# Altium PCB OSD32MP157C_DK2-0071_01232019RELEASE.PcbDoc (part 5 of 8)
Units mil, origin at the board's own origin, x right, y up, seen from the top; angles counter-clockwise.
Board outline 3976.38 x 2795.28 mil, 6 copper layers (Top Layer, Signal Layer 1, Signal Layer 2, Signal Layer 3, Signal Layer 4, Bottom Layer), stack 61.268 mil thick; 404 components, 418 nets, 1720 pads, 1233 vias.
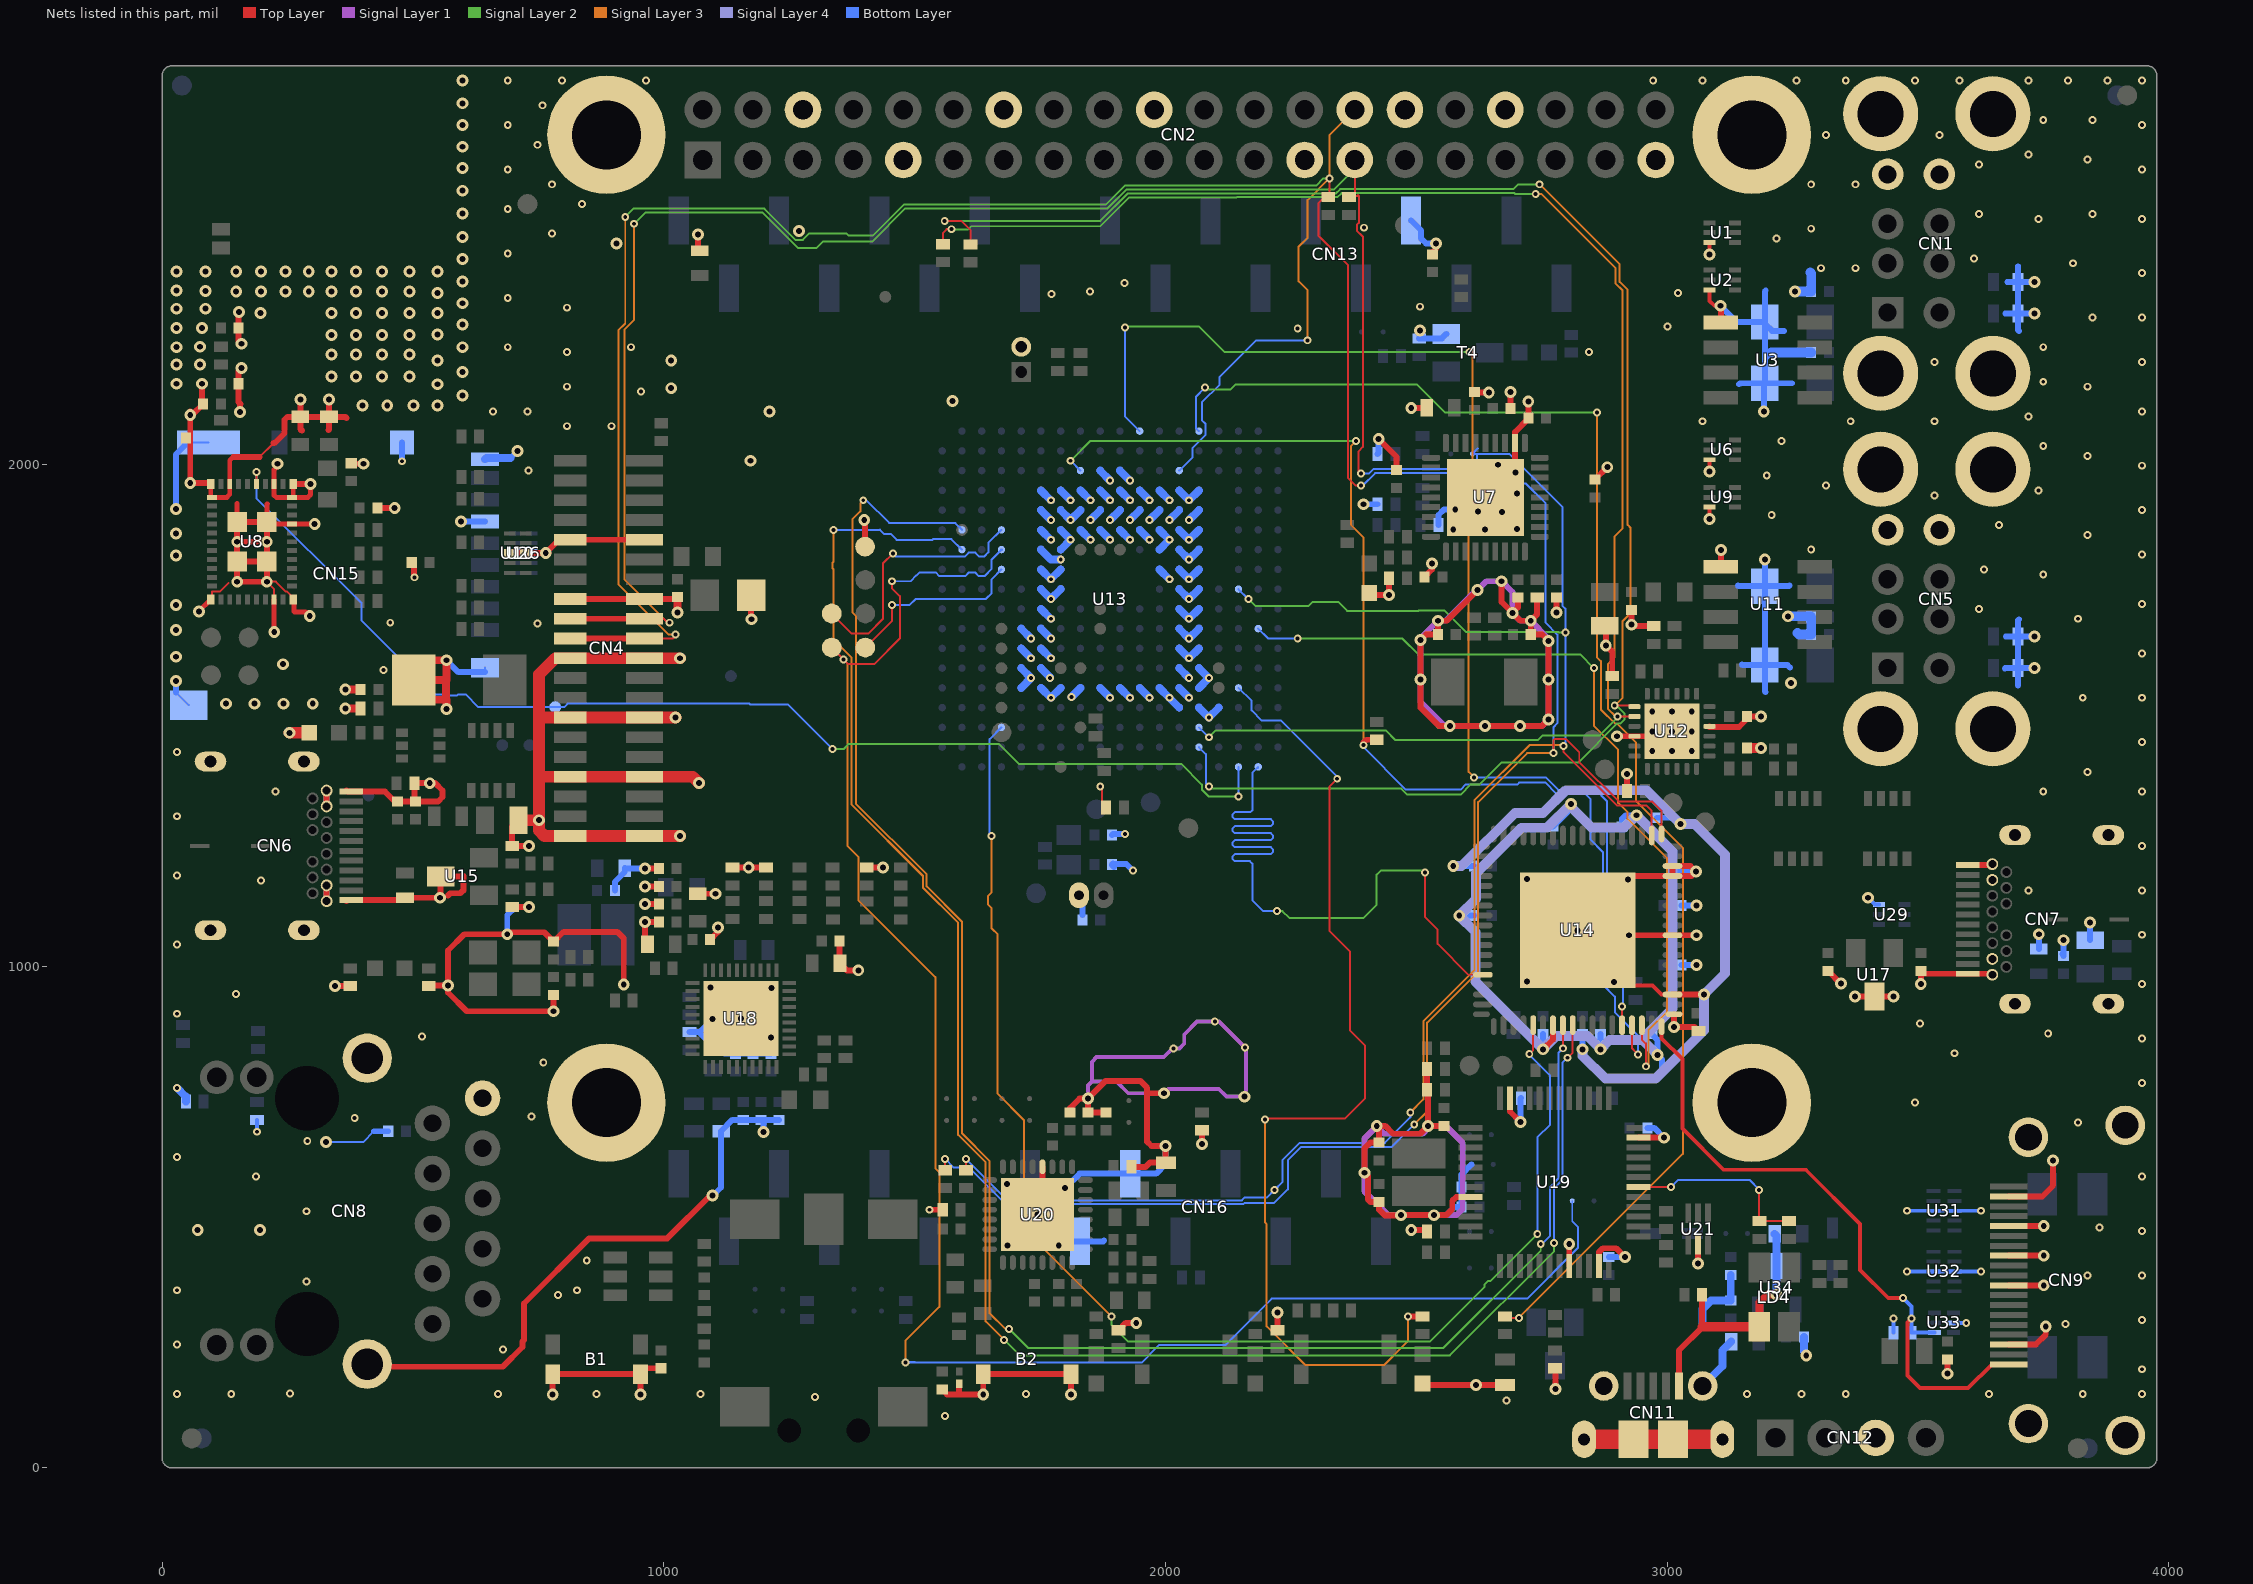
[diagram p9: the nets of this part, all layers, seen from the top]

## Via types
v1: diameter 15.75, hole 7.87, Top Layer to Bottom Layer, tented both sides, 803 vias
v2: diameter 23.62, hole 11.81, Top Layer to Bottom Layer, tented both sides, 417 vias
v3: diameter 15.75, hole 7.87, Top Layer to Bottom Layer, 13 vias

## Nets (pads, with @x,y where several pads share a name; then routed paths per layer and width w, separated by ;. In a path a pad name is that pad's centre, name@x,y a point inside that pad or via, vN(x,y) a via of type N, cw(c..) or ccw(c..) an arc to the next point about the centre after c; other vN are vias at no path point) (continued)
GND: B1.1 B1.2 B2.3 B2.4 C1.1 C7.1 C8.1 C19.1 C21.1 C23.1 C24.1 C25.1 C28.1 C29.1 C30.1 C34.1 C37.1 C38.1 C40.1 C45.1 C49.2 C50.1 C51.1 C52.2 C53.1 C54.1 C55.1 C56.1 C58.1 C59.1 C60.2 C61.2 C62.1 C65.1 C69.1 C70.2 C71.1 C74.1 C75.1 C76.2 C77.1 C78.1 C79.1 C80.1 C81.1 C82.1 C83.1 C84.1 C85.1 C86.1 C90.2 C91.2 C93.1 C94.1 C95.1 C96.2 C98.2 C99.2 C112.1 C114.1 C115.1 C117.1 C118.1 C123.1 C124.1 C133.1 C136.1 C137.1 C138.1 C140.1 C141.1 C142.1 C151.1 C154.1 C157.1 C160.1 C164.1 C166.1 C167.1 C168.1 C169.1 C170.1 C171.1 C172.1 C173.1 C174.1 C175.1 C176.1 C177.1 C178.1 C179.1 C180.1 C181.1 C182.1 C183.1 C184.1 C185.2 C186.1 C187.1 C188.1 C189.1 C190.1 CN1.B4 CN1.CH1 CN1.CH2 CN1.CH3 CN1.CH4 CN1.T4 CN2.6 CN2.9 CN2.14 CN2.20 CN2.25 CN2.30 CN2.34 CN2.39 CN3.2 CN4.1 CN4.2 CN4.7 CN4.8 CN4.13 CN4.14 CN4.19 CN4.20 CN4.25 CN4.26 CN4.31 CN4.32 CN5.B4 CN5.CH1 CN5.CH2 CN5.CH3 CN5.CH4 CN5.T4 CN6.A1 CN6.A12 CN6.B1 CN6.B12 CN6.SH1 CN6.SH2 CN6.SH3 CN6.SH4 CN7.A1 CN7.A12 CN7.B1 CN7.B12 CN7.SH1 CN7.SH2 CN7.SH3 CN7.SH4 CN8.1 CN8.15 CN8.16 CN9.2 CN9.5 CN9.8 CN9.11 CN9.17 CN9.20 CN9.21 CN9.22 CN9.23 CN11.5 CN11.6 CN11.7 CN11.8 CN11.9 CN11.10 CN11.11 CN12.3 CN13.7 CN15.6 CN15.9 CN15.10 CN15.12 CN15.13 CN15.14 CN16.6 CN16.7 CN95.2 H1.1 H2.1 H3.1 H4.1 LD1.2 LD2.2 LD4.1 LD7.2 LD8.2 R23.1 R24.1 R31.1 R36.1 R39.1 R45.1 R46.1 R48.1 R50.1 R51.1 R54.1 R57.1 R66.1 R67.1 R70.2 R80.1 R81.2 R82.1 R83.2 R84.1 R87.2 R91.1 R100.1 R110.2 R111.2 R112.1 R119.1 R129.1 R137.1 R139.1 R149.1 R155.2 R159.1 R162.1 R163.1 R164.1 R201.1 SB18.1 T4.2 TP2.1 U1.3 U2.3 U3.1 U6.3 U7.11 U7.37 U8.1 U8.12 U8.19 U8.21 U8.29 U8.32 U8.33 U8.35 U8.40 U8.42 U8.43 U8.44 U8.45 U8.46 U9.3 U10.3 U10.8 U11.1 U12.10 U12.22 U12.ep U13.D4 U13.E4 U13.E5 U13.E6 U13.E7 U13.E8 U13.E9 U13.E10 U13.E11 U13.E12 U13.E13 U13.E14 U13.E15 U13.F4 U13.F5 U13.F6 U13.F7 U13.F8 U13.F9 U13.F10 U13.F11 U13.F12 U13.F13 U13.F14 U13.F15 U13.G5 U13.G11 U13.G12 U13.G13 U13.G14 U13.G15 U13.H5 U13.H13 U13.H14 U13.H15 U13.J5 U13.J13 U13.J14 U13.J15 U13.J16 U13.K5 U13.K13 U13.K14 U13.K15 U13.K16 U13.L5 U13.L13 U13.L14 U13.L15 U13.M5 U13.M10 U13.M11 U13.M12 U13.M13 U13.M14 U13.M15 U13.N5 U13.N6 U13.N7 U13.N8 U13.N9 U13.N10 U13.N11 U13.N12 U13.N13 U13.N14 U13.N15 U13.P5 U13.P6 U13.P7 U13.P8 U14.43 U14.55 U14.57 U14.63 U14.69 U14.70 U14.e-Pad U15.3 U16.2 U17.3 U18.41 U19.8 U19.20 U19.23 U19.35 U19.47 U20.28 U20.33 U21.2 U23.2 U24.2 U25.2 U26.3 U26.8 U27.2 U28.2 U29.3 U30.2 U31.3 U31.8 U32.3 U32.8 U33.2 U34.2 U35.2 | length 28902
  Top Layer w3.54: v1@1873.16,1361.34 1872.41,1360.6 1872.41,1352.63 1873.62,1351.42 1873.62,1325.2 R201.1@1881.89,1316.93
  Top Layer w3.94: v2(56.1,2099.41) v2@56.1,2104.33 ; U8.12@96.97,1734.76 U8.12@96.97,1731.3 99.41,1731.3 99.41,1747.05 115.16,1747.05 131.89,1763.78 ; 194.54,2015.75 222.1,2043.31 ; v2(195.87,2302.17) v2@199.8,2298.23 ; U8.19@223.43,1731.3 223.43,1751.97 v2(208.66,1766.73) 226.88,1766.73 246.57,1747.05 249.02,1747.05 261.32,1734.74 U8.21@261.32,1731.3 ; v2@273.62,2131.89 v2(275.59,2129.92) ; v2@333.66,2298.23 v2(337.6,2302.17) ; CN8.16@408.97,207.09 CN8.16@408.86,207.09 CN8.16@414.17,201.77
  Top Layer w7.87: U14.e-Pad@2736.22,986.22 v2(2821.85,1071.85) ; U14.e-Pad@2891.73,1141.73 v2(2821.85,1071.85) ; U14.57@3010.83,943.9 2989.17,943.9 2971.46,961.61 2932.09,961.61 v2(2821.85,1071.85) ; v2(3084.65,1891.73) U9.3@3084.65,1915.35 ; v2(3084.65,1986.22) U6.3@3084.65,2009.84 ; U2.3@3084.65,2348.43 3084.65,2326.77 3094.49,2316.93 v2(3106.3,2316.93) ; v2(3084.65,2419.29) U1.3@3084.65,2442.91
  Top Layer w9.84: v2(73.35,1707.68) U8.12@96.97,1731.3 ; U8.42@96.97,1961.61 96.97,1937.48 U8.1@99.41,1935.04 128.95,1935.04 134.84,1940.94 U8.40@134.84,1961.61 134.84,2008.86 141.73,2015.75 ; U8.44@148.62,1807.09 U8.44@149.62,1807.09 ; U8.43@149.62,1885.83 149.62,1923.22 ; 209.65,1922.24 208.67,1921.27 U8.45@208.67,1885.83 212.61,1881.89 U8.29@258.86,1881.89 v2(304.13,1881.89) ; v2(223.43,1666.34) U8.19@223.43,1731.3 ; 223.43,1938.98 U8.35@223.43,1961.61 223.43,1990.16 230.31,1997.05 v2(230.31,2001.97) ; 227.36,1936.02 228.35,1935.04 U8.32@258.86,1935.04 ; U8.21@261.32,1731.3 262.81,1729.81 262.81,1707.67 263.91,1706.56 286.06,1706.56 v2(294.3,1698.32) ; U8.33@261.32,1961.61 261.32,1937.5 U8.32@258.86,1935.04 ; v2(295.77,1961.61) 295.77,1940.45 290.35,1935.04 U8.32@258.86,1935.04
  Top Layer w11.81: v2@56.1,2104.33 v2@56.1,2106.3 ; v2(79.72,2161.42) 79.72,2123.03 C24.1@81.69,2121.06 60.04,2099.41 v2(56.1,2099.41) v2(56.1,1963.58) 95,1963.58 U8.42@96.97,1961.61 ; 141.73,2015.75 194.54,2015.75 ; v2@152.56,2187.01 C19.1@152.56,2161.42 152.56,2125 155.51,2122.05 ; v2@152.56,2247.05 C8.1@152.56,2272.64 v2@152.56,2298.23 ; v2(155.51,2105.31) 155.51,2122.05 ; 156.5,2121.06 155.51,2122.05 ; v2(208.66,1846.46) U8.45@208.67,1885.83 U8.43@149.62,1885.83 v2(149.61,1846.46) ; 222.1,2043.31 224.41,2043.31 244.09,2062.99 244.09,2089.57 250,2095.47 C28.1@275.59,2095.47 ; U8.33@261.32,1961.61 v2(295.77,1961.61) ; v2(275.59,2129.92) C28.1@275.59,2095.47 ; 278.54,2067.91 275.59,2070.87 C28.1@275.59,2095.47 ; CN6.B1@327.95,1129.92 CN6.B1@327.95,1161.42 ; CN6.B12@327.95,1318.9 CN6.B12@327.95,1350.39 ; 331.69,2068.9 332.68,2069.88 C29.1@332.68,2095.47 ; v2(332.68,2129.92) C29.1@332.68,2095.47 ; v2(344.49,960.63) R66.1@375,960.63 ; 367.13,2093.5 365.16,2095.47 C29.1@332.68,2095.47 ; CN6.A12@367.32,1129.92 369.29,1131.89 CN6.A12@377.17,1131.89 479.33,1131.89 U16.2@484.25,1136.81 v2(554.13,1136.81) 555.12,1137.8 U15.3@555.12,1179.13 599.41,1179.13 600.39,1180.12 600.39,1151.57 594.49,1145.67 574.19,1145.67 569.57,1141.06 ; CN6.A1@367.32,1350.39 369.29,1348.43 CN6.A1@377.17,1348.43 443.9,1348.43 463.58,1328.74 C69.1@469.49,1328.74 C70.2@504.92,1328.74 ; C37.1@376.97,2002.95 377.95,2001.97 v2(401.57,2001.97) ; CN8.16@414.17,201.77 679.13,201.77 718.5,241.14 718.5,251.8 721.46,254.75 721.46,327.76 851.38,457.68 1006.92,457.68 1092.55,543.31 v2(1097.44,543.31) ; C45.1@429.13,1913.39 v2(463.58,1913.39) ; C49.2@497.64,1804.77 501.77,1800.64 501.77,1777.84 502.95,1776.66 v1(502.95,1775.59) ; R67.1@531.5,960.63 532.48,961.61 v2(569.88,961.61) ; U10.8@692.52,1823.82 U10.3@724.8,1823.82 764.72,1823.82 v2(764.8,1823.9) ; R57.1@697.83,1118.11 v2(731.3,1118.11) ; C71.1@710.63,1291.34 697.83,1278.54 R48.1@697.83,1240.16 v2(731.3,1240.16) ; v2@770.75,1823.9 v2(764.8,1823.9) ; v2(778.54,146.65) B1.2@778.54,187.01 B1.1@953.74,187.01 ; C86.1@780.51,942.91 v2(780.51,910.43) 607.28,910.43 569.88,947.83 v2(569.88,961.61) ; CN4.26@813.98,1732.28 1023.62,1732.28 C51.1@1027.56,1736.22 ; H3.1@885.83,728.35 H3.1@885.83,762.8 ; v2(920.28,963.58) 920.28,1056.1 907.48,1068.9 800.2,1068.9 C82.1@780.51,1049.21 761.81,1067.91 691.93,1067.91 v2(687.99,1063.98) 602.36,1063.98 569.88,1031.5 v2(569.88,961.61) ; v2(953.74,146.65) B1.1@953.74,187.01 ; CN4.31@961.61,1850.39 791.29,1850.39 v2(764.8,1823.9) ; v2(962.6,1124.02) C77.1@990.16,1124.02 ; v2(962.6,1159.45) C75.1@990.16,1159.45 ; v2(962.6,1194.88) C74.1@990.16,1194.88 ; C80.1@967.52,1044.29 962.6,1049.21 v2(962.6,1088.58) C78.1@990.16,1088.58 ; C114.1@994.09,198.82 965.55,198.82 B1.1@953.74,187.01 ; C76.2@1067.91,1144.69 v2(1103.35,1144.69) ; v2(1067.91,2458.66) 1067.91,2430.51 U23.2@1071.85,2426.57 ; C79.1@1092.52,1053.15 1108.27,1068.9 v2(1108.27,1077.76) ; R50.1@1136.81,1196.85 v2(1169.29,1196.85) R51.1@1203.74,1196.85 ; C52.2@1174.21,1740.16 1174.21,1690.94 v2(1175.2,1691.93) ; C81.1@1350.39,1050.2 1350.39,1006.89 C85.1@1351.38,1005.91 1365.16,992.13 v2(1387.8,992.13) ; v2(1399.61,1889.76) 1401.28,1888.09 TP2.1@1401.28,1836.68 ; R54.1@1404.53,1196.85 v2(1437.01,1196.85) ; v1(1529.53,514.76) R87.2@1556.1,514.76 ; C115.1@1555.12,156.5 1564.96,146.65 1588.58,146.65 ; U35.2@1588.58,167.81 1588.58,146.65 ; U20.28@1754.92,600.39 1754.92,514.76 v2(1745.08,504.92) 1749.02,504.92 1801.18,557.09 v2(1800.2,558.07) ; C94.1@1810.04,708.66 1810.04,717.52 1828.74,736.22 v2(1845.47,736.22) ; v2(1812.01,146.65) B2.4@1812.01,187.01 B2.3@1636.81,187.01 v2(1636.81,146.65) 1588.58,146.65 ; C96.2@1881.89,708.66 C95.1@1845.47,708.66 v2(1845.47,736.22) ; R110.2@1906.5,274.61 1921.26,289.37 v2(1941.93,289.37) ; R84.1@1932.09,600.39 1960.63,600.39 1969.49,609.25 R83.2@2000,609.25 ; v2(1997.05,747.05) 1964.57,747.05 1963.58,748.03 ; R83.2@2000.98,608.27 R83.2@2000,609.25 ; v2(2072.83,645.67) R82.1@2072.83,673.23 ; R111.2@2223.43,274.61 v2(2223.43,310.04) ; LD1.2@2406.5,1744.09 2410.43,1740.16 v2(2445.87,1740.16) R23.1@2445.87,1773.62 ; v2(2425.2,2051.18) 2460.63,2015.75 C38.1@2460.63,1989.17 ; v2(2490.15,474.41) 2518.7,474.41 R91.1@2521.65,471.46 ; v2(2490.16,2113.19) C23.1@2520.67,2113.19 ; LD7.2@2512.8,168.31 2515.75,165.35 v2(2619.09,165.35) LD8.2@2677.17,165.35 ; C50.1@2516.73,1776.57 2531.5,1791.34 v2(2531.5,1803.15) ; R80.1@2521.65,795.28 R81.2@2521.65,753.94 2523.62,751.97 v2(2523.62,682.09) ; C1.1@2534.45,2421.26 C1.1@2532.48,2419.29 2527.56,2419.29 2539.37,2431.1 v2(2539.36,2440.94) ; C93.1@2555.12,682.09 v2(2523.62,682.09) ; U19.8@2608.27,540.35 2579.72,540.35 2571.85,532.48 2571.85,515.75 2560.04,503.94 v2(2535.43,503.94) v2(2469.49,503.94) 2470.47,502.95 2437.99,502.95 2426.18,514.76 C99.2@2426.18,530.51 2408.46,530.51 2403.54,535.43 2403.54,581.69 v2(2396.65,588.58) 2396.65,636.81 2408.46,648.62 C98.2@2426.18,648.62 2426.18,682.09 2437.99,682.09 2453.74,666.34 2507.87,666.34 v2(2523.62,682.09) ; C21.1@2616.14,2144.69 2617.13,2143.7 v2(2644.68,2143.7) ; v2(2622.05,1750) 2561.02,1688.98 v2(2543.31,1688.98) C58.1@2543.31,1661.42 2519.68,1661.42 v2(2508.86,1650.59) 2508.86,1515.55 2545.08,1479.33 2750.98,1479.33 v2(2763.78,1492.13) v2(2763.78,1648.62) 2750.98,1661.42 C59.1@2728.35,1661.42 v2(2728.35,1688.98) ; U7.37@2637.8,1935.04 2696.85,1994.09 U7.11@2696.85,2043.31 2696.85,2064.96 2723.43,2091.54 C30.1@2723.43,2093.5 v2(2723.43,2125.98) ; v2(2670.28,1767.72) 2670.28,1726.38 v2(2691.93,1704.72) ; U19.47@2687.01,737.2 2687.01,710.63 v2(2707.68,689.96) ; C25.1@2687.99,2112.2 v2(2687.99,2144.69) ; C53.1@2702.76,1735.24 2702.76,1715.55 v2(2691.93,1704.72) ; R24.1@2741.14,1735.24 2741.14,1701.77 v2(2728.35,1688.98) ; v2(2752.95,834.65) 2772.64,854.33 U14.43@2772.64,882.87 ; R112.1@2776.57,198.82 2777.56,197.83 v2(2777.56,157.48) ; v2(2779.53,1705.71) C54.1@2779.53,1735.24 ; U19.20@2805.12,402.56 v2(2805.12,446.85) ; C40.1@2856.3,1970.47 v2(2880.91,1995.08) ; U19.23@2864.17,402.56 2864.17,430.12 2872.05,437.99 2898.62,437.99 v2(2916.34,420.28) ; C55.1@2875.98,1679.13 2877.95,1677.17 v2(2877.95,1639.76) 2890.75,1626.97 R36.1@2890.75,1578.74 ; U14.e-Pad@2891.73,1141.73 2930.12,1180.12 U14.69@3010.83,1180.12 ; v2(2900.59,1458.66) U12.10@2935.04,1458.66 2960.63,1458.66 v2(2970.47,1468.5) ; R46.1@2920.28,1349.41 v2(2920.28,1383.86) ; v2(2924.21,1062.01) U14.63@3010.83,1062.01 v2(3059.06,1062.01) ; C56.1@2929.13,1710.63 v2(2929.13,1681.1) 2932.09,1678.15 R31.1@2973.43,1678.15 ; U19.35@2942.91,658.46 v2(2994.09,658.46) ; U14.57@3010.83,943.9 v2(3073.82,943.9) v2@3072.83,944.88 ; U14.55@3013.78,904.53 v2(3013.78,878.94) 3055.12,878.94 R70.2@3062.99,871.06 ; CN11.5@3023.62,163.39 3023.62,234.25 3070.87,281.5 3069.88,282.48 R100.1@3069.88,345.47 ; v2(3062.01,407.48) U21.2@3062.01,444.69 ; U12.22@3084.65,1478.35 3084.65,1477.17 3143.5,1477.17 3159.45,1493.11 C62.1@3159.45,1498.03 v2(3187.01,1498.03) ; v2(3106.3,2316.93) 3107.28,2315.94 U3.1@3107.28,2283.66 ; U11.1@3107.28,1796.46 v2(3107.28,1829.72) ; C83.1@3320.87,991.14 v2(3346.46,965.55) ; v2(3375,939.96) U17.3@3413.39,939.96 v2(3451.77,939.96) ; v2(3505.91,964.57) C84.1@3505.91,991.14 3511.81,985.24 CN7.A1@3599.21,985.24 3646.46,985.24 CN7.B12@3648.43,983.27 ; v2(3559.06,187.99) C112.1@3559.06,216.54 ; CN7.A12@3599.21,1201.77 3646.46,1201.77 CN7.B1@3648.43,1203.74 ; CN9.17@3681.1,246.06 3735.24,246.06 3754.92,265.75 v2(3754.92,282.34) ; CN9.11@3681.1,364.17 v2(3750.98,364.17) ; CN9.8@3681.1,423.23 v2(3750.98,423.23) ; CN9.5@3681.1,482.28 v2(3750.98,482.28) ; CN9.2@3681.1,541.34 3748.03,541.34 3769.68,562.99 v2(3769.68,613.19) ; U8.44@149.62,1807.09 U8.46@208.67,1807.09 ; U8.44@149.62,1807.09 148.62,1807.09 149.61,1806.1 v2(149.61,1766.73) v2(208.66,1766.73) U8.46@208.67,1807.09 ; U8.44@149.62,1807.09 v2(149.61,1846.46) ; v2(149.61,1846.46) v2(208.66,1846.46) U8.46@208.67,1807.09 ; C28.1@275.59,2095.47 C29.1@332.68,2095.47 ; C70.2@504.92,1328.74 550.2,1328.74 559.06,1337.6 559.06,1350.39 544.29,1365.16 v2(533.46,1365.16) R45.1@502.95,1365.16 502.95,1330.71 C70.2@504.92,1328.74 ; v2(1845.47,736.22) 1880.91,771.65 1949.8,771.65 1963.58,757.87 1963.58,748.03 ; 1963.58,748.03 1963.58,650.39 1972.24,641.73 v2(2000,641.73) R83.2@2000,609.25 ; v2(2691.93,1704.72) 2707.68,1688.98 v2(2728.35,1688.98) ; U14.69@3010.83,1180.12 U14.70@3010.83,1199.8 3046.75,1199.8 v2(3057.58,1188.98) 3048.72,1180.12 U14.69@3010.83,1180.12
  Top Layer w15.75: v2(365.16,1513.78) R39.1@395.67,1513.78 ; v2(365.16,1552.17) C61.2@395.67,1552.17 ; C60.2@481.3,1591.54 C60.2@501.97,1570.87 ; C60.2@500.98,1531.5 565.94,1531.5 ; v2(566.93,1512.8) 566.93,1526.57 563.98,1529.53 565.94,1531.5 ; 566.93,1531.5 565.94,1531.5 ; v2(566.93,1610.24) 566.93,1570.87 ; v2@567.91,1610.24 501.97,1610.24 C60.2@501.97,1570.87 ; v2(1027.56,1705.71) C51.1@1027.56,1736.22 ; LD4.1@3184.06,281.5 3184.06,329.72 3199.8,345.47 v2(3218.5,345.47) ; C60.2@501.97,1570.87 566.93,1570.87 ; 565.94,1531.5 565.94,1569.88 566.93,1570.87
  Top Layer w19.68: 3070.87,281.5 LD4.1@3184.06,281.5 ; C65.1@3159.45,1435.04 v2(3187.01,1435.04)
  Top Layer w23.62: v2(253.94,1465.55) LD2.2@293.31,1465.55 ; C71.1@710.63,1291.34 v2(751.6,1291.34) ; v2(1023.62,1496.06) 753.47,1496.06 751.6,1494.19 ; v2(1032.48,1259.84) 762.24,1259.84 751.6,1270.48 v2(751.6,1291.34) ; v2(1032.48,1614.17) 809.33,1614.17 809.22,1614.29 783.58,1614.29 751.6,1582.31 751.6,1494.19 ; v2(1070.08,1365.75) 1057.87,1377.95 752.46,1377.95 751.6,1378.81 ; v2(751.6,1291.34) 751.6,1378.81 ; 751.6,1378.81 751.6,1494.19
  Top Layer w39.37: CN11.9@2834.65,57.09 CN11.10@2933.07,57.09 CN11.11@3011.81,57.09 CN11.8@3110.24,57.09
  Signal Layer 1 w7.87: v2(1845.47,736.22) 1845.47,762.2 1853.54,770.28 ; 1853.54,770.28 1853.54,809.58 1862.86,818.9 1996.65,818.9 2013.98,836.22 v1(2015.94,836.22) 2027.76,836.22 2037.6,846.06 2037.6,864.37 2062.99,889.76 v1(2098.43,889.76) 2107.09,889.76 v1(2158.66,838.19) 2160.63,836.22 2160.63,743.31 v2(2157.48,740.16) 2122.05,740.16 2106.3,755.91 2005.91,755.91 v2(1997.05,747.05) 1925.98,747.05 1902.76,770.28 1853.54,770.28
  Signal Layer 1 w11.81: v2(2421.26,682.09) v2@2421.26,681.1 ; v2@2421.75,681.59 v2@2421.26,681.1 ; v2@2522.83,681.3 v2@2523.62,681.3 ; v2(2523.62,682.09) v2@2523.62,681.3 ; v2@2620.28,1748.23 2617.91,1748.23 2558.66,1688.98 v2(2543.31,1688.98) 2508.86,1654.53 v2(2508.86,1650.59) v2(2508.86,1571.85) 2508.86,1526.57 2556.1,1479.33 v2(2566.93,1479.33) v2(2636.81,1479.33) v2(2706.69,1479.33) 2750.98,1479.33 v2(2763.78,1492.13) v2(2763.78,1571.85) v2(2763.78,1648.62) 2763.78,1653.54 v2(2728.35,1688.98) 2707.68,1688.98 v2(2691.93,1704.72) 2691.93,1746.06 v2(2670.28,1767.72) 2639.76,1767.72 v2(2622.05,1750) ; v2@2421.26,681.1 2421.26,680.12 2435.04,666.34 2512.8,666.34 2523.62,677.17 v2@2523.62,681.3 ; v2@2421.26,681.1 2396.65,656.5 v2(2396.65,588.58) 2396.65,551.97 2444.69,503.94 v2(2469.49,503.94) v2(2535.43,503.94) 2580.31,503.94 2592.72,516.34 2592.72,648.23 2559.65,681.3 v2@2523.62,681.3
  Signal Layer 2 w7.87: 2543.06,1478.49 v2@2556,1478.49
  Signal Layer 2 w11.81: CN6.B1@327.95,1129.92 CN6.B1@327.95,1161.42 ; CN6.B12@327.95,1318.9 CN6.B12@327.95,1350.39
  Signal Layer 3 w11.81: CN6.B1@327.95,1129.92 CN6.B1@327.95,1161.42 ; CN6.B12@327.95,1318.9 CN6.B12@327.95,1350.39
  Signal Layer 4 w11.81: CN6.B1@327.95,1129.92 CN6.B1@327.95,1161.42 ; CN6.B12@327.95,1318.9 CN6.B12@327.95,1350.39
  Signal Layer 4 w19.68: v2(2573.82,1199.8) 2590.55,1199.8 2696.75,1306 2753.06,1306 2798.04,1350.98 2959.06,1350.98 v2(3026.57,1283.46) 3054.92,1283.46 3115.35,1223.03 3115.35,985.43 v2(3073.82,943.9) 3073.82,872.44 2977.56,776.18 2877.17,776.18 2831.69,821.65 v2(2831.69,834.65) ; 2950.98,855.91 3011.02,915.94 3011.02,1229.13 v2(2938.98,1301.18) 2914.37,1276.57 2849.1,1276.57 2808.27,1317.41 v2(2808.27,1323.43) 2761.02,1276.18 2709.84,1276.18 2619.29,1185.63 2619.29,1134.45 v2(2585.83,1100.98) 2618.31,1068.5 2618.31,969.29 v2(2752.95,834.65) 2779.13,860.83 2841.7,860.83 2867.13,835.4 v2(2867.13,834.65) 2885.43,852.95 2951.18,852.95 v2(2980.65,823.49)
  Bottom Layer w3.94: CN15.13@27.56,1546.26 CN15.13@53.15,1520.67 ; CN15.12@51.18,2044.29 CN15.12@92.52,2044.29 ; v2(326.77,649.61) 400.59,649.61 422.24,671.26 ; CN15.14@643.7,1586.61 CN15.14@643.7,1595.47
  Bottom Layer w7.87: v1(188.98,670.28) R163.1@188.98,693.9 ; v2(3400.59,1136.81) 3414.37,1123.03 U29.3@3422.24,1123.03 ; R164.1@3451.77,269.69 v1(3451.77,298.23) ; v1(3478.35,391.73) U32.8@3531.5,391.73 U32.3@3572.83,391.73 v1(3625.98,391.73) ; v1(3478.35,512.8) U31.8@3531.5,512.8 U31.3@3572.83,512.8 v1(3625.98,512.8) ; U33.2@3570.87,289.37 v1(3596.46,289.37)
  Bottom Layer w11.81: CN15.13@27.56,1546.26 v2(27.56,1568.9) ; v2(27.56,1911.42) 27.56,2020.67 CN15.12@51.18,2044.29 ; CN6.B1@327.95,1129.92 CN6.B1@327.95,1161.42 ; CN6.B12@327.95,1318.9 CN6.B12@327.95,1350.39 ; 422.24,671.26 C183.1@450.79,671.26 ; v1(478.35,2006.89) CN15.10@478.35,2044.29 ; v2(566.93,1610.24) 590.55,1586.61 CN15.14@643.7,1586.61 ; v2(595.47,1886.81) 589.57,1886.81 CN15.6@643.7,1886.81 ; v2(687.99,1063.98) 687.99,1102.36 703.74,1118.11 v2(731.3,1118.11) ; 694.49,2013.39 v2(708.66,2027.56) ; U26.3@704.33,1823.82 U26.8@736.61,1823.82 764.72,1823.82 v2(764.8,1823.9) ; C157.1@902.56,1151.57 902.56,1168.31 922.24,1187.99 C151.1@922.24,1195.87 923.23,1194.88 v2(962.6,1194.88) ; R155.2@1051.18,869.09 1071.85,869.09 ; v2(1097.44,543.31) 1098.43,543.31 1114.17,559.06 C180.1@1114.17,671.26 1136.81,693.9 C179.1@1158.46,693.9 C178.1@1193.9,693.9 C178.1@1196.06,693.9 ; v2(1199.02,669.88) 1199.02,690.94 C178.1@1196.06,693.9 ; v2(1213.58,858.27) C174.1@1213.58,825.79 C175.1@1178.15,825.79 C176.1@1142.72,825.79 1121.06,825.79 C173.1@1098.43,848.43 1090.55,848.43 1070.87,868.11 1071.85,869.09 ; C177.1@1229.33,693.9 C178.1@1196.06,693.9 ; 1776.57,449.8 1778.58,451.81 CN16.7@1829.92,451.81 1876.02,451.81 1877.95,453.74 ; v2(1800.2,558.07) 1828.92,586.79 CN16.6@1929.92,586.79 1981.48,586.79 2000,605.31 v2(2000,641.73) ; CN3.2@1827.76,1141.73 1834.65,1134.84 C7.1@1834.65,1102.36 ; C90.2@1893.7,1261.81 1895.67,1263.78 v3(1919.29,1263.78) ; C91.2@1895.67,1204.72 C91.2@1894.92,1203.97 ; C91.2@1897.83,1197.64 1893.7,1201.77 C91.2@1893.7,1202.76 C91.2@1894.92,1203.97 ; v3(1935.04,1190.94) 1922.01,1203.97 C91.2@1894.92,1203.97 ; v2(2394.68,1921.26) R137.1@2423.23,1921.26 ; R129.1@2423.23,2021.65 2425.2,2023.62 v2(2425.2,2051.18) ; CN13.7@2489.92,2486.77 2509.84,2466.85 2509.84,2450.79 2519.68,2440.94 v2(2539.36,2440.94) ; v2(2507.87,2267.71) 2507.87,2253.93 R119.1@2505.91,2251.97 2551.18,2251.97 T4.2@2560.04,2260.83 ; v2(2535.43,503.94) 2560.04,503.94 2576.77,520.67 C184.1@2590.55,520.67 C182.1@2590.55,560.04 2590.55,585.63 SB18.1@2610.24,605.31 ; R139.1@2544.29,1879.92 2544.29,1899.61 2555.12,1910.43 v2(2577.76,1910.43) ; v2(2573.82,1199.8) C154.1@2615.16,1199.8 ; v2(2585.83,1100.98) 2614.76,1100.98 C164.1@2615.16,1101.38 ; v2(2707.68,689.96) 2707.68,736.22 R159.1@2708.66,737.2 ; v2(2752.95,834.65) C172.1@2752.95,865.16 ; C142.1@2772.64,1278.54 2808.27,1314.17 v2(2808.27,1323.43) ; v2(2831.69,834.65) C171.1@2831.69,865.16 ; v2(2867.13,834.65) C170.1@2867.13,865.16 ; C186.1@2883.86,420.28 v2(2916.34,420.28) ; C141.1@2910.43,1278.54 2910.43,1294.29 2917.32,1301.18 v2(2938.98,1301.18) ; C181.1@2960.63,678.15 2974.41,678.15 v2(2994.09,658.46) ; C169.1@2969.49,865.16 2980.65,854 v2(2980.65,823.49) 2990.16,813.98 2990.16,794.29 ; C140.1@2980.31,1296.26 3013.78,1296.26 v2(3026.57,1283.46) ; v2(3013.78,878.94) v2@3014.76,879.92 ; R149.1@3017.72,1191.93 3054.63,1191.93 v2(3057.58,1188.98) ; C168.1@3028.54,1002.95 v2(3059.06,1002.95) ; C160.1@3028.54,1121.06 v2(3059.06,1121.06) ; v2(3106.3,2316.93) 3138.78,2284.45 C118.1@3194.88,2284.45 ; 3141.73,1758.86 3142.72,1757.87 C133.1@3194.88,1757.87 ; 3143.7,2160.43 3145.67,2162.4 C124.1@3194.88,2162.4 ; 3149.61,1601.38 3150.59,1600.39 C138.1@3194.88,1600.39 ; v2(3192.91,2106.3) 3192.91,2160.43 C124.1@3194.88,2162.4 ; v2(3194.88,1811.02) C133.1@3194.88,1757.87 ; 3195.87,1547.24 3194.88,1548.23 C138.1@3194.88,1600.39 ; 3196.85,2347.44 3194.88,2345.47 C118.1@3194.88,2284.45 ; 3207.68,2223.43 3194.88,2210.63 ; 3233.27,2266.73 3209.65,2266.73 C118.1@3194.88,2281.5 ; 3244.09,1758.86 3243.11,1757.87 C133.1@3194.88,1757.87 ; 3245.08,1595.47 3240.16,1600.39 C138.1@3194.88,1600.39 ; 3249.02,2162.4 C124.1@3194.88,2162.4 ; C136.1@3286.42,1697.83 C136.1@3287.4,1696.85 ; 3673.23,1593.5 3674.21,1594.49 U28.2@3699.8,1594.49 ; 3674.21,2301.18 U25.2@3699.8,2301.18 ; 3675.2,1657.48 U27.2@3699.8,1657.48 ; 3678.15,2364.17 U24.2@3699.8,2364.17 ; 3699.8,1560.04 U28.2@3699.8,1594.49 ; 3699.8,2395.67 U24.2@3699.8,2364.17 ; 3701.77,1691.93 3699.8,1689.96 U27.2@3699.8,1657.48 ; 3701.77,2266.73 3699.8,2268.7 U25.2@3699.8,2301.18 ; v2(3732.28,1594.49) U28.2@3699.8,1594.49 ; v2(3732.28,1657.48) U27.2@3699.8,1657.48 ; v2(3732.28,2301.18) U25.2@3699.8,2301.18 ; v2(3732.28,2364.17) U24.2@3699.8,2364.17 ; U30.2@3741.14,1034.45 v2(3741.14,1063.98) ; C167.1@3788.39,1024.61 C167.1@3790.35,1022.64 ; C167.1@3790.35,1020.67 C167.1@3790.35,1022.64 ; v2(3790.35,1052.17) C167.1@3790.35,1022.64 ; C166.1@3843.5,1052.17 v2(3843.5,1087.6) ; 1071.85,869.09 v2(1097.44,894.69) 1071.85,869.09 ; C138.1@3194.88,1600.39 C133.1@3194.88,1757.87 ; C124.1@3194.88,2162.4 3194.88,2210.63 ; 3194.88,2210.63 C118.1@3194.88,2281.5 ; C118.1@3194.88,2281.5 C118.1@3194.88,2284.45 ; U28.2@3699.8,1594.49 U27.2@3699.8,1657.48 ; U25.2@3699.8,2301.18 U24.2@3699.8,2364.17
  Bottom Layer w15.75: v1(29.53,757.87) 47.24,740.16 R162.1@47.24,730.31 ; CN15.9@643.7,2010.83 646.26,2013.39 694.49,2013.39 ; U13.P5@1712.6,1555.12 v1(1732.28,1574.8) U13.P6@1712.6,1594.49 ; U13.P7@1712.6,1633.86 v1(1732.28,1614.17) ; U13.P8@1712.6,1673.23 v1(1732.28,1653.54) ; U13.N5@1751.97,1555.12 v1(1771.65,1535.43) U13.M5@1791.34,1555.12 ; U13.N6@1751.97,1594.49 1769.68,1576.78 v1(1769.68,1574.8) ; U13.N7@1751.97,1633.86 v1(1771.65,1614.17) ; U13.N8@1751.97,1673.23 v1(1771.65,1653.54) ; U13.N9@1751.97,1712.6 v1(1771.65,1692.91) ; U13.N10@1751.97,1751.97 v1(1771.65,1732.28) U13.M10@1791.34,1751.97 ; U13.N11@1751.97,1791.34 v1(1771.65,1771.65) U13.M11@1791.34,1791.34 ; U13.N12@1751.97,1830.71 1771.66,1811.02 v1(1791.33,1811.02) ; U13.N13@1751.97,1870.08 v1(1771.65,1850.39) ; U13.N14@1751.97,1909.45 v1(1771.65,1889.76) ; U13.N15@1751.97,1948.82 v1(1771.65,1929.13) ; U13.M12@1791.34,1830.71 v1(1811.02,1850.39) U13.M13@1791.34,1870.08 ; U13.M14@1791.34,1909.45 v1(1811.02,1889.76) U13.L14@1830.71,1909.45 ; U13.M15@1791.34,1948.82 v1(1811.02,1929.13) ; v1(1812.58,1536.99) U13.L5@1830.71,1555.12 ; U13.L13@1830.71,1870.08 v1(1850.39,1850.39) ; U13.L15@1830.71,1948.82 v1(1850.39,1929.13) ; v1(1850.39,1889.76) U13.K14@1870.08,1909.45 ; U13.K5@1870.08,1555.12 v1(1889.76,1535.43) ; U13.K13@1870.08,1870.08 v1(1889.76,1850.39) ; U13.K15@1870.08,1948.82 v1(1889.76,1929.13) ; U13.K16@1870.08,1988.19 v1(1889.76,1968.5) ; v1(1889.76,1889.76) U13.J14@1909.45,1909.45 ; U13.J5@1909.45,1555.12 v1(1929.13,1535.43) ; U13.J13@1909.45,1870.08 v1(1929.13,1850.39) ; U13.J15@1909.45,1948.82 v1(1929.13,1929.13) ; U13.J16@1909.45,1988.19 v1(1929.13,1968.5) ; v1(1929.13,1889.76) U13.H14@1948.82,1909.45 ; U13.H5@1948.82,1555.12 v1(1968.5,1535.43) ; U13.H13@1948.82,1870.08 v1(1968.5,1850.39) ; U13.H15@1948.82,1948.82 v1(1968.5,1929.13) ; v1(1968.5,1889.76) U13.G14@1988.19,1909.45 ; U13.G5@1988.19,1555.12 v1(2007.87,1535.43) U13.F4@2027.56,1515.75 ; U13.G11@1988.19,1791.34 v1(2007.87,1771.65) ; U13.G12@1988.19,1830.71 v1(2007.87,1850.39) U13.G13@1988.19,1870.08 ; U13.G15@1988.19,1948.82 v1(2007.87,1929.13) ; v1(2007.87,1889.76) U13.F14@2027.56,1909.45 ; U13.F5@2027.56,1555.12 v1(2047.24,1535.43) ; U13.F6@2027.56,1594.49 v1(2047.24,1574.8) ; U13.F7@2027.56,1633.86 v1(2047.24,1614.17) U13.E7@2066.93,1633.86 ; U13.F8@2027.56,1673.23 v1(2047.24,1653.54) U13.E8@2066.93,1673.23 ; U13.F9@2027.56,1712.6 v1(2047.24,1692.91) U13.E9@2066.93,1712.6 ; U13.F10@2027.56,1751.97 v1(2047.24,1732.28) U13.E10@2066.93,1751.97 ; U13.F11@2027.56,1791.34 v1(2047.24,1771.65) U13.E11@2066.93,1791.34 ; U13.F12@2027.56,1830.71 v1(2047.24,1811.02) U13.E12@2066.93,1830.71 ; U13.F13@2027.56,1870.08 v1(2047.24,1850.39) U13.E13@2066.93,1870.08 ; U13.F15@2027.56,1948.82 v1(2047.24,1929.13) U13.E15@2066.93,1948.82 ; v1(2047.24,1889.76) U13.E14@2066.93,1909.45 ; U13.E4@2066.93,1515.75 v1(2086.61,1496.06) U13.D4@2106.3,1515.75 ; U13.E5@2066.93,1555.12 v1(2086.61,1574.8) U13.E6@2066.93,1594.49 ; CN11.7@3070.87,163.39 3110.24,202.76 3110.24,234.25 C190.1@3127.95,251.97 ; 3070.87,281.5 3070.87,316.93 3087.6,333.66 C188.1@3126.97,333.66 ; C188.1@3126.97,333.66 C187.1@3126.97,384.84 ; C185.2@3214.57,466.54 3218.5,462.6 U34.2@3218.5,402.56 v2(3218.5,345.47) ; C189.1@3272.64,260.83 3272.64,232.28 3277.56,227.36 v2(3277.56,224.41)
  Bottom Layer w19.68: 3207.68,2223.43 C123.1@3287.4,2223.43 ; v2(3241.14,1697.83) C136.1@3286.42,1697.83 ; v2(3254.92,2345.47) C117.1@3287.4,2345.47 3287.4,2380.91 3285.43,2382.87 ; 3259.84,1664.37 3262.8,1661.42 C137.1@3287.4,1661.42 C136.1@3287.4,1696.85
  other v1: 1561.02,103.35 2680.12,134.84 1301.18,141.73 29.53,147.64 137.8,147.64 669.29,147.64 866.14,147.64 1072.83,147.64 1722.44,147.64 3159.45,147.64 3267.72,147.64 3356.3,147.64 3641.73,147.64 3828.74,147.64 3946.85,147.64 254.92,148.62 3946.85,196.85 679.13,236.22 29.53,246.06 3794.29,287.4 3946.85,295.28 789.37,344.49 29.53,354.33 826.77,354.33 287.4,372.05 3838.58,383.86 3946.85,383.86 846.46,413.39 3946.85,472.44 3862.2,479.33 287.4,511.81 187.01,580.71 3946.85,580.71 29.53,620.08 289.37,651.57 3818.9,688.98 383.88,697.87 736.22,700.79 3494.09,728.35 3946.85,767.72 759.84,808.07 3572.83,826.77 3946.85,856.3 517.72,860.24 3759.84,866.14 3503.94,885.83 29.53,905.51 147.64,944.88 3946.85,964.57 29.53,1043.31 3946.85,1062.99 3720.47,1151.57 3946.85,1151.57 196.85,1171.26 29.53,1181.1 3946.85,1240.16 29.53,1299.21 226.38,1348.43 3750,1348.43 3946.85,1348.43 1870.08,1358.27 3838.58,1387.8 29.53,1427.17 3946.85,1446.85 3828.74,1535.43 3946.85,1535.43 440.94,1590.55 3946.85,1624.02 748.03,1683.07 454.72,1685.04 3818.9,1692.91 3622.05,1712.6 3946.85,1722.44 3750,1781.5 3631.89,1791.34 3946.85,1820.87 3287.4,1830.71 3838.58,1860.24 3661.42,1879.92 3208.66,1899.61 3946.85,1909.45 3533.46,1938.98 3740.16,1948.82 3316.93,1958.66 3198.82,1978.35 730.31,1988.19 3946.85,1998.03 3838.58,2017.72 3750,2037.4 3228.35,2047.24 807.09,2076.77 895.67,2076.77 3070.87,2086.61 3366.14,2086.61 3533.46,2086.61 3720.47,2096.46 659.45,2106.3 728.35,2106.3 3946.85,2106.3 954.72,2145.67 807.09,2155.51 3838.58,2155.51 3750,2165.35 3533.46,2204.72 3946.85,2204.72 807.09,2224.41 2844.49,2224.41 688.98,2234.25 935.04,2234.25 3750,2234.25 2263.78,2271.65 3000.98,2275.59 3848.43,2293.31 3946.85,2293.31 807.09,2312.99 2507.87,2314.96 688.98,2332.68 1772.64,2340.55 3021.65,2342.52 1849.41,2345.47 1918.31,2362.2 3946.85,2381.89 3307.09,2391.73 3375.98,2391.73 3809.06,2401.57 3612.2,2411.42 688.98,2421.26 3218.5,2450.79 777.56,2460.63 3287.4,2470.47 2395.67,2472.44 3740.16,2490.16 3946.85,2490.16 3622.05,2500 3848.43,2500 688.98,2509.84 836.61,2519.69 777.56,2559.06 3287.4,2559.06 3375.98,2559.06 688.98,2588.58 3946.85,2588.58 3622.05,2598.43 3838.58,2608.27 3720.47,2618.11 748.03,2637.8 3316.93,2657.48 3543.31,2657.48 688.98,2677.17 3946.85,2677.17 3750,2687.01 3848.43,2687.01 757.87,2716.54 688.98,2765.75 797.24,2765.75 964.57,2765.75 2972.44,2765.75 3070.87,2765.75 3257.87,2765.75 3356.3,2765.75 3494.09,2765.75 3582.68,2765.75 3720.47,2765.75 3799.21,2765.75 3877.95,2765.75 3946.85,2765.75
  other v2: 1685.04,443.9 1787.4,443.9 70.87,474.41 194.88,474.41 1684.06,565.94 1153.54,895.67 1214.57,956.69 1093.5,957.68 2894.68,968.5 2720.47,969.49 2922.24,1173.23 2720.47,1174.21 2970.47,1429.13 3009.84,1429.13 3049.21,1429.13 3009.84,1468.5 3049.21,1468.5 2970.47,1507.87 3009.84,1507.87 3049.21,1507.87 126.97,1523.62 184.06,1523.62 242.13,1523.62 300.2,1523.62 3247.05,1564.96 241.14,1602.36 27.56,1617.13 27.56,1670.28 27.56,1720.47 27.56,1818.9 27.56,1863.19 2573.82,1871.06 2636.81,1871.06 2700.79,1872.05 2671.26,1905.51 2623.03,1906.5 2700.79,1942.91 2697.83,1984.25 2663.39,2000 1173.23,2007.87 1210.63,2106.3 399.61,2118.11 448.82,2118.11 500.98,2118.11 549.21,2118.11 1575.79,2126.97 598.43,2137.8 1014.76,2152.56 549.21,2160.43 28.54,2161.42 337.6,2176.18 386.81,2176.18 437.99,2176.18 493.11,2176.18 598.43,2185.04 158.46,2192.91 28.54,2199.8 75.79,2199.8 549.21,2207.68 1014.76,2207.68 337.6,2219.49 386.81,2219.49 437.99,2219.49 493.11,2219.49 28.54,2234.25 598.43,2234.25 75.79,2235.24 158.46,2241.14 337.6,2258.86 386.81,2258.86 437.99,2258.86 493.11,2258.86 549.21,2259.84 28.54,2272.64 79.72,2272.64 598.43,2279.53 386.81,2302.17 437.99,2302.17 493.11,2302.17 549.21,2302.17 153.54,2304.13 28.54,2311.02 86.61,2311.02 598.43,2321.85 549.21,2342.52 147.64,2345.47 196.85,2345.47 246.06,2345.47 292.32,2345.47 337.6,2345.47 386.81,2345.47 437.99,2345.47 493.11,2345.47 86.61,2346.46 28.54,2347.44 598.43,2365.16 28.54,2384.84 86.61,2384.84 147.64,2384.84 196.85,2384.84 246.06,2384.84 292.32,2384.84 337.6,2384.84 386.81,2384.84 437.99,2384.84 493.11,2384.84 549.21,2384.84 598.43,2410.43 905.51,2440.94 598.43,2453.74 1269.88,2466.14 598.43,2500.98 598.43,2546.26 598.43,2591.54 598.43,2633.86 598.43,2677.17 598.43,2720.47 598.43,2765.75
HDMI_CEC: U13.H18 U14.50 | length 2531.2
  Top Layer w3.94: U14.50@2910.43,882.87 v1(2910.43,920.28)
  Signal Layer 2 w3.94: v1(1919.29,2273.62) 1921.26,2275.59 2066.93,2275.59 2118.11,2224.41 v1(2606.29,2224.41)
  Signal Layer 3 w3.94: v1(2606.29,2224.41) 2612.2,2218.49 2612.2,1986.22 2604.33,1978.35 2604.33,1387.6 v1(2615.35,1376.57)
  Bottom Layer w3.94: v1(1919.29,2273.62) 1919.29,2096.46 U13.H18@1948.82,2066.93 ; v1(2615.35,1376.57) 2758.09,1376.57 2782.7,1351.97 2857.85,1351.97 2880.17,1329.64 2880.17,1008.07 2912.4,975.84 2912.4,922.24 v1(2910.43,920.28)
HDMI_INT: U13.B8 U14.52 | length 1658.7
  Top Layer w3.94: 2949.8,853.94 U14.52@2949.8,882.87 ; 2950,853.94 2957.87,846.06 v1(2957.87,800.79)
  Signal Layer 2 w3.94: v1(2263.78,1653.54) 2472.44,1653.54 2503.94,1622.05 2826.77,1622.05 v1(2854.33,1594.49)
  Signal Layer 3 w3.94: v1(2854.33,1594.49) 2854.33,1479.87 2902.56,1431.64 2902.56,1325.79 2921.26,1307.09 2921.26,1293.84 3000,1215.1 3000,909.45 2962.93,872.38 2962.93,805.84 v1(2957.87,800.79)
  Bottom Layer w3.94: U13.B8@2185.04,1673.23 2204.72,1653.54 v1(2263.78,1653.54)
HDMI_NRST: R40.2 U13.L16 U14.51 | length 2390.7
  Top Layer w3.94: U14.51@2930.12,882.87 2930.12,836.42 2937.99,828.54 v1(2942.13,824.41)
  Top Layer w11.81: v1(2395.1,1440.84) 2395.1,1446.29 2400.59,1451.77 R40.2@2421.26,1451.77
  Signal Layer 2 w3.94: v1(1811.02,2007.87) 1850.39,2047.24 v1(2379.92,2047.24)
  Signal Layer 3 w3.94: v1(2379.92,2047.24) 2370.08,2037.4 2370.08,1879.47 2395.1,1854.45 v1(2395.1,1440.84)
  Bottom Layer w3.94: v1(1811.02,2007.87) U13.L16@1830.71,1988.19 ; v1(2395.1,1440.84) 2395.1,1436.59 2479.53,1352.17 2588.39,1352.17 2599.02,1362.8 2701.97,1362.8 2705.92,1366.75 2756.78,1366.75 2779.44,1344.09 2836.61,1344.09 2847.64,1333.07 2847.64,1252.56 2872.3,1227.9 2872.3,963.13 2895.87,939.57 2895.87,908.07 2942.13,861.81 v1(2942.13,824.41)
HPD: CN9.19 R164.2 U14.54 U33.4 | length 1325.1
  Top Layer w7.87: U14.54@2989.17,879.92 2989.17,856.3 3030.51,814.96 3030.51,676.63 3112.65,594.49 3276.57,594.49 3384.84,486.22 3384.84,394.69 3440.94,338.58 v1(3470.47,338.58) ; v1(3487.2,298.23) 3479.33,290.35 3479.33,184.06 3503.94,159.45 3600.39,159.45 3647.64,206.69 CN9.19@3681.1,206.69
  Bottom Layer w7.87: v1(3470.47,338.58) 3487.2,321.85 v1(3487.2,298.23) R164.2@3487.2,269.69 U33.4@3533.46,269.69
I2C1_SCL: CN2.28 CN4.21 CN4.22 R1.2 R85.2 SB8.1 U13.F16 U14.1 | length 7494.1
  Top Layer w3.94: CN4.21@961.61,1653.54 1017.72,1653.54 1023.62,1659.45 v1(1023.62,1661.42) ; R85.2@1561.02,593.5 v1(1561.02,616.14) ; v1(2326.77,2570.87) 2326.77,2535.43 R1.2@2324.8,2533.46 2316.93,2533.46 2305.12,2521.65 2305.12,2456.97 2364.17,2397.92 2364.17,1973.43 2379.33,1958.27 v1(2389.76,1958.27) ; v1(2773.62,1425.2) 2773.62,1451.06 2775.32,1452.76 2799.01,1452.76 2825,1426.77 2825,1407.09 2903.35,1328.74 2969.49,1328.74 2989.17,1309.06 U14.1@2989.17,1263.78
  Top Layer w11.81: CN4.22@813.98,1653.54 CN4.21@961.61,1653.54
  Signal Layer 2 w3.94: v1(923.23,2494.09) 939.57,2510.43 1200.54,2510.43 1262.54,2448.43 1277.22,2448.43 1289.82,2461.02 1363.98,2461.02 1368.31,2456.69 1416.76,2456.69 1478.57,2518.5 1881.44,2518.5 1919.39,2556.45 2300.54,2556.45 2314.96,2570.87 v1(2326.77,2570.87)
  Signal Layer 3 w3.94: v1(923.23,2494.09) 923.23,2281.5 909.45,2267.72 909.45,1761.81 1009.84,1661.42 v1(1023.62,1661.42) ; v1(1561.02,616.14) 1560.43,616.73 v1@1561.22,616.73 ; v1(2283.46,2248.03) 2283.46,2347.69 2265.75,2365.41 2265.75,2435.04 2283.46,2452.76 2283.46,2527.56 v1(2326.77,2570.87) 2326.77,2656.69 CN2.28@2377.56,2707.48 ; v1(2496.06,685.04) 2521.65,710.63 2521.65,887.8 2623.23,989.37 2623.23,1327.25 2721.17,1425.2 v1(2773.62,1425.2)
  Bottom Layer w3.94: v1(1561.02,616.14) 1578.42,598.74 1608.63,598.74 1678.94,528.43 1679.5,528.43 1682.04,525.89 2155.45,525.89 2157.99,528.43 2216.9,528.43 2244.09,555.62 2244.09,613.34 2270.95,640.2 2451.22,640.2 v1(2496.06,685.04) ; U13.F16@2027.56,1988.19 2053.64,2014.27 2053.64,2033.06 2080.22,2059.64 2080.22,2081.2 2072.83,2088.58 2072.83,2124.21 2108.27,2159.65 2108.27,2175 2181.3,2248.03 v1(2283.46,2248.03) ; v1(2389.76,1958.27) 2392.91,1958.27 2417.91,1983.27 2625,1983.27 2629.92,1978.35 2629.92,1966.54 2625.98,1962.6 ; 2612.2,1962.6 2625.98,1962.6 ; v1(2773.62,1425.2) 2773.62,1476.91 2781.5,1484.79 2781.5,1661.42 2757.87,1685.04 2757.87,1923.23 2718.5,1962.6 2625.98,1962.6
I2C1_SDA: CN2.27 CN4.23 CN4.24 R2.2 R86.2 SB7.1 U13.C10 U14.2 | length 7162.7
  Top Layer w3.94: CN4.23@961.61,1692.91 1000.13,1692.91 1008,1685.04 v1(1011.81,1685.04) ; R86.2@1602.36,593.5 v1(1602.36,616.14) ; CN2.27@2377.56,2607.48 2377.56,2534.06 2378.94,2535.43 2385.83,2535.43 ; 2384.11,2537.6 2385.83,2535.88 2385.83,2535.43 ; v1(2389.76,1982.87) 2385.04,1982.87 2385.04,2026.77 2393.7,2035.43 2393.7,2454.92 2381.89,2466.73 2381.89,2478.15 2385.83,2482.09 2385.83,2535.43 ; v1(2793.31,1438.98) 2793.31,1427.64 2900.08,1320.87 2958.66,1320.87 2969.49,1310.04 U14.2@2969.49,1260.83
  Top Layer w11.81: CN4.24@813.98,1692.91 CN4.23@961.61,1692.91
  Signal Layer 2 w3.94: v1(940.94,2480.31) 963.19,2502.56 1197.27,2502.56 1268.17,2431.66 1303.94,2431.66 1317.15,2444.88 1415.53,2444.88 1481.67,2511.02 1884.54,2511.02 1922.09,2548.58 2335.98,2548.58 2377.56,2590.16 CN2.27@2377.56,2607.48 ; v1(2165.35,1732.28) 2179.13,1718.5 2285.43,1718.5 2293.31,1726.38 2344.49,1726.38 2362.2,1708.66 2504.13,1708.66 2504.58,1709.11 2556.64,1709.11 2599.41,1666.34 2783.46,1666.34 2784.45,1665.35 v1(2797.24,1665.35)
  Signal Layer 3 w3.94: v1(940.94,2480.31) 940.94,2288.63 921.26,2268.95 921.26,1852.64 921.26,1771.78 1008,1685.04 v1(1011.81,1685.04) ; v1(2488.19,708.66) 2514.17,734.65 2514.17,890.89 2615.75,992.47 2615.75,1330.91 2725.79,1440.94 2791.34,1440.94 v1(2793.31,1438.98)
  Bottom Layer w3.94: v1(1602.36,616.14) 1685.14,533.37 2152.35,533.37 2158.35,539.37 2202.76,539.37 v1(2217.52,554.13) 2233.24,569.85 2233.24,613.62 2267.69,648.07 2437.44,648.07 2488.19,698.82 v1(2488.19,708.66) ; U13.C10@2145.67,1751.97 v1(2165.35,1732.28) ; v1(2389.76,1982.87) 2406.38,1982.87 2414.65,1991.14 2617.13,1991.14 2621.06,1995.08 2621.06,2021.65 ; 2623.03,2032.48 SB7.1@2612.2,2021.65 2621.06,2021.65 ; v1(2793.31,1438.98) 2797.24,1442.91 v1(2797.24,1665.35) 2797.24,1713.05 2791.34,1718.95 2791.34,1915.8 2685.49,2021.65 2621.06,2021.65
I2C4_SCL: R5.2 U12.7 U13.E2 | length 3497.1
  Top Layer w3.94: v1(1560.04,2486.22) 1592.72,2486.22 1611.61,2467.32 R5.2@1611.61,2438.98 ; v1(2895.67,1519.69) 2933.07,1519.69 U12.7@2935.04,1517.72
  Signal Layer 2 w3.94: v1(1560.04,2486.22) 1870.32,2486.22 1924.8,2540.7 2339.91,2540.7 2348.43,2549.21 2693.7,2549.21 2703.54,2559.05 2743.89,2559.05 2745.26,2557.68 2747.24,2557.68 2746.06,2558.86 v1(2746.06,2559.05) ; v1(2086.61,1358.27) 2090.55,1354.33 2470.47,1354.33 2482.28,1342.52 2588.39,1342.52 2608.66,1362.8 2626.57,1362.8 2669.9,1406.12 2822.57,1406.12 2900.7,1484.25 2907.28,1484.25 2915.35,1492.32 2915.35,1503.74 2899.41,1519.69 v1(2895.67,1519.69)
  Signal Layer 3 w3.94: v1(2746.06,2559.05) 2746.06,2558.86 2905.51,2399.41 2905.51,2364.37 2921.26,2348.62 2921.26,1879.92 2927.17,1874.02 2927.17,1704.19 2911.42,1688.44 2911.42,1535.43 v1(2895.67,1519.69)
  Bottom Layer w3.94: U13.E2@2066.93,1437.01 2080.71,1423.23 2080.71,1364.17 v1(2086.61,1358.27)
I2C4_SDA: R7.2 U12.8 U13.E3 | length 3298.6
  Top Layer w3.94: R7.2@1556.89,2439.57 1556.89,2462.4 1563.98,2469.49 v1(1573.82,2469.49) ; v1(2901.57,1498.03) U12.8@2935.04,1498.03
  Signal Layer 2 w3.94: v1(1573.82,2469.49) 1574.21,2469.09 1606.48,2469.09 1612.77,2475.39 1870.07,2475.39 1927.5,2532.83 2142.17,2532.83 2142.57,2533.22 2343.01,2533.22 2351.13,2541.34 2695.56,2541.34 2697.33,2539.57 2733.07,2539.57 2738.18,2544.68 v1(2738.18,2539.37) ; v1(2086.61,1456.69) 2100.39,1470.47 2438.98,1470.47 2458.66,1450.79 2742.13,1450.79 2751.97,1460.63 2865.94,1460.63 2901.57,1496.26 v1(2901.57,1498.03)
  Signal Layer 3 w3.94: v1(2738.18,2539.37) 2750.01,2539.37 2897.64,2391.73 2897.64,2361.11 2911.42,2347.33 2911.42,1873.03 2895.67,1857.28 2895.67,1616.14 2881.89,1602.36 2881.89,1513.98 2897.84,1498.03 v1(2901.57,1498.03)
  Bottom Layer w3.94: U13.E3@2066.93,1476.38 v1(2086.61,1456.69)
I2S2_CK: U13.U12 U14.45 | length 3692.1
  Top Layer w3.94: v1(2801.91,817.84) 2812.01,827.94 U14.45@2812.01,882.87
  Signal Layer 2 w3.94: v1(1678.35,255.51) 1709.45,224.41 2566.93,224.41 2774.8,432.28 v1(2774.8,448.43)
  Signal Layer 3 w3.94: v1(1338.58,1870.08) 1338.58,1806.89 1336.61,1804.92 1336.61,1793.51 1338.58,1791.54 1338.58,1651.18 1374.02,1615.75 1374.02,1322.83 1516.73,1180.12 1516.73,1156.5 1586.61,1086.61 1586.61,664.27 1641.73,609.15 1641.73,292.13 v1(1678.35,255.51)
  Bottom Layer w3.94: v1(1338.58,1870.08) 1430.4,1870.08 1430.75,1870.43 1438.98,1862.2 1452.22,1862.2 1464.03,1850.39 1535.43,1850.39 1536.91,1851.87 1573.33,1851.87 U13.U12@1594.49,1830.71 ; v1(2774.8,448.43) 2774.8,557.37 2791.54,574.1 2791.54,807.47 v1(2801.91,817.84)
I2S2_SDO: U13.R3 U14.41 | length 2708.7
  Top Layer w3.94: v1(2725.39,825.2) 2733.27,833.07 U14.41@2733.27,882.87
  Signal Layer 2 w3.94: v1(1892.91,301.77) 1892.91,285.24 1926.18,251.97 2527.17,251.97 2635.83,360.63 2635.83,364.96 2643.9,373.03 2648.23,373.03 v1(2741.34,466.14)
  Signal Layer 3 w3.94: v1(1653.54,1259.84) 1653.54,1147.62 1646.46,1140.53 1646.46,1123.25 1653.54,1116.16 1653.54,1075.48 1665.35,1063.67 1665.35,746.07 1717.72,693.7 1717.72,476.97 v1(1892.91,301.77)
  Bottom Layer w3.94: v1(1653.54,1259.84) 1649.78,1263.61 1649.78,1452.92 U13.R3@1673.23,1476.38 ; v1(2725.39,825.2) 2725.39,823.43 2766.93,781.89 2766.93,684.65 2741.34,659.06 v1(2741.34,466.14)
I2S2_WS: U13.U13 U14.44 | length 3640.9
  Top Layer w3.94: v1(2792.32,836.65) U14.44@2792.32,882.87
  Signal Layer 2 w3.94: v1(1688.19,277.17) 1726.18,239.17 2554.13,239.17 2748.23,433.27 v1(2748.23,446.46)
  Signal Layer 3 w3.94: v1(1397.64,1929.13) 1391.73,1923.23 1391.73,1906.94 1375.98,1891.2 1375.98,1705.71 1383.07,1698.62 1383.07,1324.36 1524.21,1183.22 1524.21,1159.59 1594.49,1089.32 1594.49,666.98 1649.21,612.25 1649.21,309 1681.05,277.17 v1(1688.19,277.17)
  Bottom Layer w3.94: v1(1397.64,1929.13) 1404,1929.13 1449.28,1883.86 1482.09,1883.86 1482.58,1883.37 1581.2,1883.37 U13.U13@1594.49,1870.08 ; v1(2748.23,446.46) 2750.2,446.46 2766.93,463.19 2766.93,560.63 2783.66,577.36 2783.66,827.99 v1(2792.32,836.65)
JTDI: TP4.1 U13.R13 | length 527.1
  Top Layer w3.94: TP4.1@1334.84,1703.35 1374.8,1663.39 1407.48,1663.39 1437.01,1692.91 1437.01,1803.15 v1(1456.69,1822.83)
  Bottom Layer w3.94: v1(1456.69,1822.83) 1462.6,1816.93 1599.9,1816.93 1607.78,1824.8 1620.97,1824.8 1628.35,1817.42 1639.36,1817.42 1647.15,1825.2 1647.15,1844 U13.R13@1673.23,1870.08
JTDO_TRACESWO: SB19.2 TP8.1 U13.R12 | length 3600.8
  Top Layer w3.94: TP8.1@1334.84,1635.43 v1(1358.27,1612.01) 1367.91,1602.36 1419.29,1602.36 1470.47,1653.54 1470.47,1738.19 1454.72,1753.94 v1(1454.72,1767.72)
  Signal Layer 3 w3.94: v1(1358.27,1612.01) 1366.14,1604.13 1366.14,1240.16 1387.8,1218.5 1387.8,1131.89 1541.34,978.35 1541.34,597.25 1549.21,589.37 1549.21,383.91 1549.21,321.31 1482.28,254.39 v1(1482.28,210.63)
  Bottom Layer w3.94: v1(1454.72,1767.72) 1491.93,1767.72 1503.74,1779.53 1503.94,1779.53 1509.84,1785.43 1542.23,1785.43 1549.61,1778.05 1601.08,1778.05 1608.47,1785.43 1620.43,1785.43 1627.81,1778.05 1639.36,1778.05 1653.54,1792.23 1653.54,1811.02 U13.R12@1673.23,1830.71 ; 1500,210.63 1579.28,210.63 1579.67,210.24 1952.42,210.24 1987.07,244.88 2118.95,244.88 2211.87,337.8 2721.12,337.8 2822.83,439.51 2822.83,480.12 2811.02,491.93 SB19.2@2811.02,532.48
  Bottom Layer w4.72: v1(1482.28,210.63) 1500,210.63
JTRST: TP9.1 U13.R11 | length 371
  Top Layer w3.94: TP9.1@1401.77,1635.43 1454.72,1688.39 v1(1454.72,1720.47)
  Bottom Layer w3.94: v1(1454.72,1720.47) 1490.16,1720.47 1501.97,1732.28 1641.73,1732.28 1653.54,1744.09 1653.54,1771.65 U13.R11@1673.23,1791.34
LED_B: R108.1 U13.E18 | length 2951.4
  Top Layer w3.94: R108.1@2677.17,302.17 2680.12,299.21 v1(2704.72,299.21)
  Signal Layer 2 w3.94: v1(2078.74,2153.54) 2078.74,2149.61 2129.72,2149.61 2139.56,2159.44 2501.97,2159.44 2557.09,2104.33 v1(2860.24,2104.33)
  Signal Layer 3 w3.94: v1(2704.72,299.21) 3031.5,625.99 3031.5,1236.22 2937.99,1329.72 2937.99,1446.31 2900.06,1484.25 2895.87,1484.25 2868.11,1512.01 2868.11,1608.27 2860.24,1616.14 v1(2860.24,2104.33)
  Bottom Layer w3.94: U13.E18@2066.93,2066.93 2061.02,2072.83 2061.02,2135.83 v1(2078.74,2153.54)
LED_STLINK: R89.2 R90.2 U19.30 | length 377.5
  Top Layer w3.94: U19.30@2942.91,560.04 v1(3007.87,560.04) ; v1(3183.07,554.13) 3183.07,495.08 3185.04,493.11 R89.2@3184.06,492.13 R90.2@3243.11,492.13
  Bottom Layer w3.94: v1(3007.87,560.04) 3021.65,573.82 3165.35,573.82 3183.07,556.1 v1(3183.07,554.13)
LED_Y: R107.1 U13.C5 | length 2000.5
  Top Layer w3.94: v1(2198.82,694.88) 2200.79,696.85 2358.27,696.85 2397.64,736.22 2397.64,842.52 2368.11,872.05 2368.11,1029.53 2326.77,1070.87 2326.77,1358.27 v1(2342.52,1374.02)
  Top Layer w11.81: v1(2483.27,302.17) R107.1@2512.8,302.17
  Signal Layer 3 w3.94: v1(2198.82,694.88) 2198.82,489.37 2201.97,486.22 2201.97,282.45 2279.11,205.31 2436.22,205.31 2483.27,252.36 v1(2483.27,302.17)
  Bottom Layer w3.94: U13.C5@2145.67,1555.12 2171.75,1529.04 2171.75,1510.24 2192.33,1489.67 2230.61,1489.67 2342.52,1377.75 v1(2342.52,1374.02)
LPO_32: TP26.1 U8.37 U13.C1 | length 2381.4
  Top Layer w3.94: U8.37@187.99,1961.61 v1(187.99,1985.23)
  Signal Layer 2 w3.94: v1(1336.61,1433.07) 1358.27,1433.07 1368.9,1443.7 1667.77,1443.7 1707.93,1403.54 2031.5,1403.54 2072.83,1362.2 2072.83,1352.56 2086.81,1338.58 v1(2145.67,1338.58)
  Bottom Layer w3.94: v1(187.99,1985.23) 187.99,1933.28 397.67,1723.6 397.67,1688.94 544.29,1542.32 562.24,1542.32 565,1539.57 587.35,1539.57 590.1,1542.32 604.84,1542.32 630.43,1516.73 TP26.1@783.46,1516.73 801.57,1516.73 808.46,1523.62 1170.87,1523.62 1172.83,1521.65 1248.03,1521.65 v1(1336.61,1433.07) ; v1(2145.67,1338.58) U13.C1@2145.67,1397.64
LTDC_B0: U13.B1 U14.32 | length 1505.5
  Top Layer w3.94: v1(2517.71,1187.01) 2517.71,1097.98 2542.52,1073.17 2542.52,1044.83 2604.08,983.27 U14.32@2632.87,983.27
  Signal Layer 2 w3.94: v1(2222.44,1110.24) 2233.27,1110.24 2247.05,1096.46 2395.33,1096.46 2421.26,1122.39 2421.26,1182.87 2429.33,1190.94 2513.77,1190.94 v1(2517.71,1187.01)
  Bottom Layer w3.94: U13.B1@2185.04,1395.24 U13.B1@2185.04,1397.64 2173.23,1385.83 2173.23,1350.39 2173.23,1311.02 2169.49,1307.28 2138.34,1307.28 2133.46,1302.41 2133.46,1298.22 2138.34,1293.35 2173.23,1293.35 2210.08,1293.35 2214.96,1288.47 2214.96,1284.29 2210.08,1279.41 2173.23,1279.41 2138.34,1279.41 2133.46,1274.53 2133.46,1270.35 2138.34,1265.47 2173.23,1265.47 2210.08,1265.47 2214.96,1260.59 2214.96,1256.41 2210.08,1251.54 2173.23,1251.54 2138.34,1251.54 2133.46,1246.66 2133.46,1242.48 2138.34,1237.6 2173.23,1237.6 2210.08,1237.6 2214.96,1232.72 2214.96,1228.54 2210.08,1223.66 2173.23,1223.66 2138.34,1223.66 2133.46,1218.78 2133.46,1214.6 2138.34,1209.72 2168.35,1209.72 2173.23,1204.85 2173.23,1202.76 2173.23,1131.89 2194.88,1110.24 v1(2222.44,1110.24) v1@2218.69,1106.5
